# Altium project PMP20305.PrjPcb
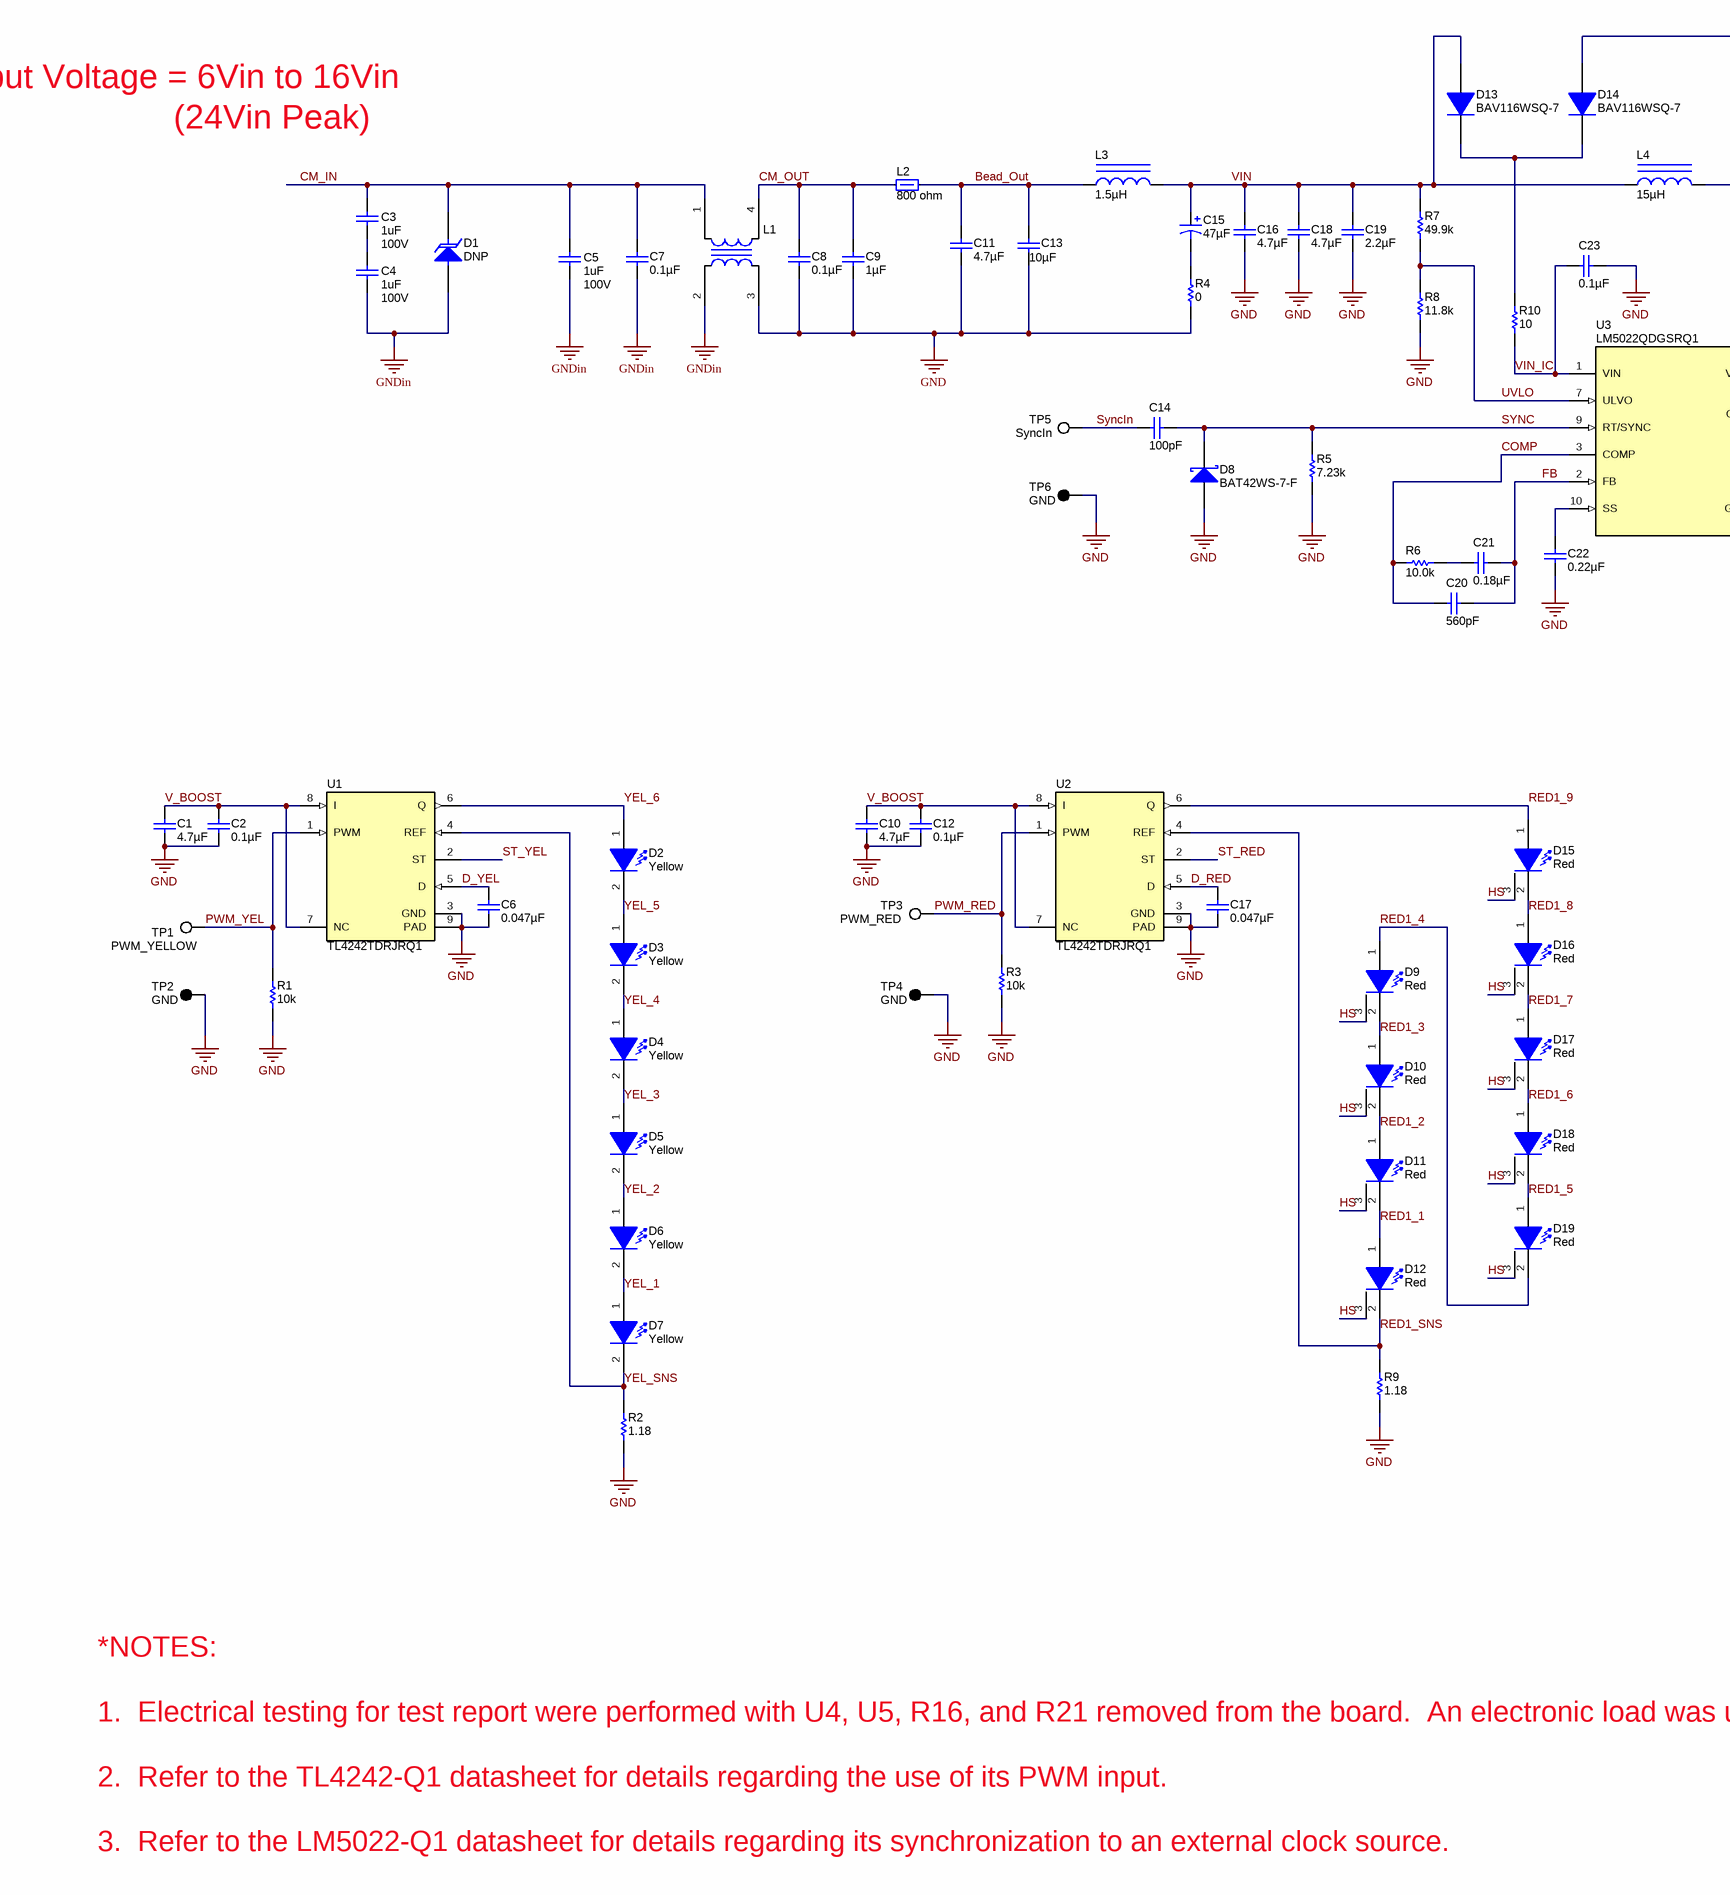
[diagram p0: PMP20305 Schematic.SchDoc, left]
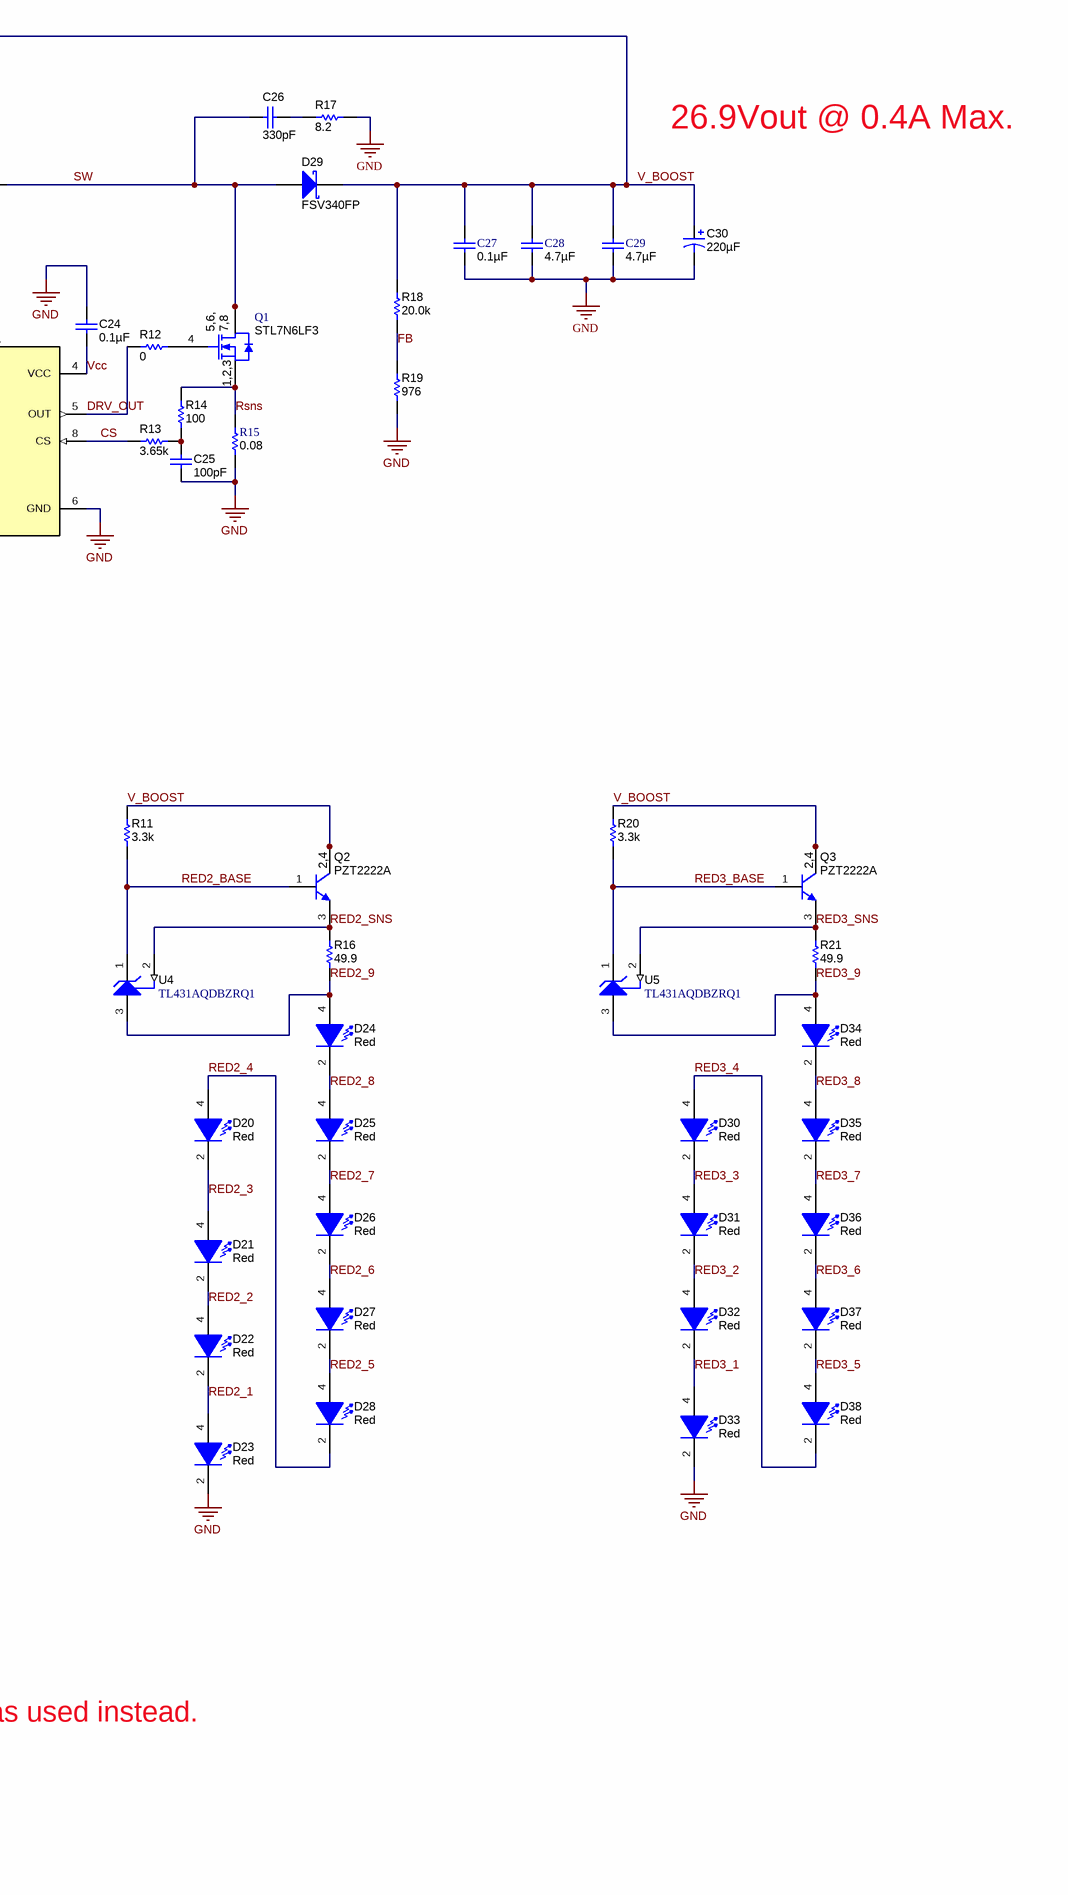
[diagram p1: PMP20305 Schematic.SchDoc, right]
CopyrightYear: 2016; PCB_Rev: A; PRJ_Number: PMP20305; PRJ_Title: LM5022 Non-Sync Boost with LED Drivers; SCH_Rev: A; TechSupport: http://www.ti.com/support; TID: PMP20305
2 sheets, 122 parts. Net scope: global (net labels, ports and power ports of the same name join across sheets).
Board file: PMP20305 PCB.PcbDoc
Sheets:
  PMP20305 Schematic.SchDoc
  PMP20305_EVM_Hardware.SchDoc

## Sheet PMP20305 Schematic.SchDoc
size 558 x 431 mm; Date: Not shown in title block; ApprovedBy: Not shown in title block; CheckedBy: Not shown in title block; Author: Not shown in title block; CompanyName: Not shown in title block; Engineer: Not shown in title block; Organization: Not shown in title block; Address1: Not shown in title block; Address2: Not shown in title block; Address3: Not shown in title block; Address4: Not shown in title block; DocumentNumber: 1; Revision: Use project parameter SCH_Rev; SheetNumber: 1; SheetTotal: 2; PageSetup: Record=PageOptions¦CenterHorizontal=True¦CenterVertical=True¦PrintScale=1.00¦XCorrection=1.00¦YCorrection=1.00¦PrintKind=0¦BorderSize=5000000¦LeftOffset=0¦BottomOffset=0¦Orientation=2¦PaperLength=1000¦PaperWidth=1000¦Scale=100¦PaperSource=15¦PrintQuality=600¦MediaType=1¦DitherType=10¦PaperKind=Letter¦PrintScaleMode=1

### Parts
C1  ValueDisplayed: 4.7µF  [1206_180]  (hidden comment: GRM31CR71H475KA12L)
C2  ValueDisplayed: 0.1µF  [0805_HV]  (hidden comment: 08055C104JAT2A)
C3  value 1uF  Value1: 100V  [0805]  (hidden comment: CGA4J3X7S2A105K125AB)
C4  value 1uF  Value1: 100V  [0805]  (hidden comment: CGA4J3X7S2A105K125AB)
C5  value 1uF  Value1: 100V  [0805]  (hidden comment: CGA4J3X7S2A105K125AB)
C6  ValueDisplayed: 0.047µF  [0603]  (hidden comment: GRM188R71C473KA01D)
C7  ValueDisplayed: 0.1µF  [0805_HV]  (hidden comment: CGA4J2X7R2A104K125AA)
C8  ValueDisplayed: 0.1µF  [0603]  (hidden comment: GRM188R71H104KA93D)
C9  ValueDisplayed: 1µF  [0603]  (hidden comment: UMK107AB7105KA-T)
C10  ValueDisplayed: 4.7µF  [1206_180]  (hidden comment: GRM31CR71H475KA12L)
C11  ValueDisplayed: 4.7µF  [1206_180]  (hidden comment: GRM31CR71H475KA12L)
C12  ValueDisplayed: 0.1µF  [0805_HV]  (hidden comment: 08055C104JAT2A)
C13  ValueDisplayed: 10µF  [1210_280]  (hidden comment: C3225X7R1H106M250AC)
C14  ValueDisplayed: 100pF  [0603]  (hidden comment: 06035A101JAT2A)
C15  ValueDisplayed: 47µF  [SM_RADIAL_G]  (hidden comment: EEE-FC1H470P)
C16  ValueDisplayed: 4.7µF  [1206_180]  (hidden comment: GRM31CR71H475KA12L)
C17  ValueDisplayed: 0.047µF  [0603]  (hidden comment: GRM188R71C473KA01D)
C18  ValueDisplayed: 4.7µF  [1206_180]  (hidden comment: GRM31CR71H475KA12L)
C19  ValueDisplayed: 2.2µF  [0805_HV]  (hidden comment: C2012X7R1H225K125AC)
C20  ValueDisplayed: 560pF  [0603]  (hidden comment: GRM1885C1E561JA01D)
C21  ValueDisplayed: 0.18µF  [0603]  (hidden comment: GRM188R71C184KA01D)
C22  ValueDisplayed: 0.22µF  [0603]  (hidden comment: GCM155R71C224KE02)
C23  ValueDisplayed: 0.1µF  [0805_HV]  (hidden comment: 08055C104JAT2A)
C24  ValueDisplayed: 0.1µF  [0603]  (hidden comment: 885012206071)
C25  ValueDisplayed: 100pF  [0603]  (hidden comment: 06035A101JAT2A)
C26  ValueDisplayed: 330pF  [0805_HV]  (hidden comment: C0805C331J1GACTU)
C27  ValueDisplayed: 0.1µF  [0603]  (hidden comment: CGA3E3X8R1H104K080AB)
C28  ValueDisplayed: 4.7µF  [1206_190]  (hidden comment: C3216X7R1H475M160AC)
C29  ValueDisplayed: 4.7µF  [1206_190]  (hidden comment: C3216X7R1H475M160AC)
C30  ValueDisplayed: 220µF  [SM_RADIAL_G]  (hidden comment: EEE-FC1V221P)
D1  DNP  [SMB]
D2  value Yellow  [LED_goldendragon]  (hidden comment: LY-W5SM)
D3  value Yellow  [LED_goldendragon]  (hidden comment: LY-W5SM)
D4  value Yellow  [LED_goldendragon]  (hidden comment: LY-W5SM)
D5  value Yellow  [LED_goldendragon]  (hidden comment: LY-W5SM)
D6  value Yellow  [LED_goldendragon]  (hidden comment: LY-W5SM)
D7  value Yellow  [LED_goldendragon]  (hidden comment: LY-W5SM)
D8  BAT42WS-7-F  [SOD-323]
D9  value Red  [LH CP7P_RED]  (hidden comment: LH CP7P-2T3T-1)
D10  value Red  [LH CP7P_RED]  (hidden comment: LH CP7P-2T3T-1)
D11  value Red  [LH CP7P_RED]  (hidden comment: LH CP7P-2T3T-1)
D12  value Red  [LH CP7P_RED]  (hidden comment: LH CP7P-2T3T-1)
D13  BAV116WSQ-7  [SOD-323]
D14  BAV116WSQ-7  [SOD-323]
D15  value Red  [LH CP7P_RED]  (hidden comment: LH CP7P-2T3T-1)
D16  value Red  [LH CP7P_RED]  (hidden comment: LH CP7P-2T3T-1)
D17  value Red  [LH CP7P_RED]  (hidden comment: LH CP7P-2T3T-1)
D18  value Red  [LH CP7P_RED]  (hidden comment: LH CP7P-2T3T-1)
D19  value Red  [LH CP7P_RED]  (hidden comment: LH CP7P-2T3T-1)
D20  value Red  [LED_PowerTOPLED_GF]  (hidden comment: LR-E6SF)
D21  value Red  [LED_PowerTOPLED_GF]  (hidden comment: LR-E6SF)
D22  value Red  [LED_PowerTOPLED_GF]  (hidden comment: LR-E6SF)
D23  value Red  [LED_PowerTOPLED_GF]  (hidden comment: LR-E6SF)
D24  value Red  [LED_PowerTOPLED_GF]  (hidden comment: LR-E6SF)
D25  value Red  [LED_PowerTOPLED_GF]  (hidden comment: LR-E6SF)
D26  value Red  [LED_PowerTOPLED_GF]  (hidden comment: LR-E6SF)
D27  value Red  [LED_PowerTOPLED_GF]  (hidden comment: LR-E6SF)
D28  value Red  [LED_PowerTOPLED_GF]  (hidden comment: LR-E6SF)
D29  FSV340FP  [SOD-123HE]
D30  value Red  [LED_PowerTOPLED_GF]  (hidden comment: LR-E6SF)
D31  value Red  [LED_PowerTOPLED_GF]  (hidden comment: LR-E6SF)
D32  value Red  [LED_PowerTOPLED_GF]  (hidden comment: LR-E6SF)
D33  value Red  [LED_PowerTOPLED_GF]  (hidden comment: LR-E6SF)
D34  value Red  [LED_PowerTOPLED_GF]  (hidden comment: LR-E6SF)
D35  value Red  [LED_PowerTOPLED_GF]  (hidden comment: LR-E6SF)
D36  value Red  [LED_PowerTOPLED_GF]  (hidden comment: LR-E6SF)
D37  value Red  [LED_PowerTOPLED_GF]  (hidden comment: LR-E6SF)
D38  value Red  [LED_PowerTOPLED_GF]  (hidden comment: LR-E6SF)
L1  ACM9070-701-2PL-TL01  [TDK_ACM9070]  (value not drawn)
L2  value 800 ohm  [1206]  (hidden comment: HR2220V801R-10)
L3  ValueDisplayed: 1.5µH  [WE-TPC_6823]  (hidden comment: 7440620015)
L4  ValueDisplayed: 15µH  [MSS1246T]  (hidden comment: MSS1246T-153MLB)
Q1  STL7N6LF3  [PowerFLAT5x6_R]
Q2  PZT2222A  [SOT-223]
Q3  PZT2222A  [SOT-223]
R1  ValueDisplayed: 10k  [0603]  (hidden comment: CRCW060310K0JNEA)
R2  ValueDisplayed: 1.18  [0805_HV]  (hidden comment: CRCW08051R18FKEA)
R3  ValueDisplayed: 10k  [0603]  (hidden comment: CRCW060310K0JNEA)
R4  ValueDisplayed: 0  [1206]  (hidden comment: CRCW12060000Z0EA)
R5  ValueDisplayed: 7.23k  [0603]  (hidden comment: RT0603DRE077K23L)
R6  ValueDisplayed: 10.0k  [0603]  (hidden comment: CRCW060310K0FKEA)
R7  ValueDisplayed: 49.9k  [0603]  (hidden comment: CRCW060349K9FKEA)
R8  ValueDisplayed: 11.8k  [0603]  (hidden comment: CRCW060311K8FKEA)
R9  ValueDisplayed: 1.18  [0805_HV]  (hidden comment: CRCW08051R18FKEA)
R10  ValueDisplayed: 10  [0603L]  (hidden comment: CRCW060310R0JNEA)
R11  ValueDisplayed: 3.3k  [0603]  (hidden comment: RC0603JR-073K3L)
R12  ValueDisplayed: 0  [0603]  (hidden comment: CRCW06030000Z0EA)
R13  ValueDisplayed: 3.65k  [0603]  (hidden comment: CRCW06033K65FKEA)
R14  ValueDisplayed: 100  [0603]  (hidden comment: CRCW0603100RJNEA)
R15  ValueDisplayed: 0.08  [2512]  (hidden comment: CRA2512-FZ-R080ELF)
R16  ValueDisplayed: 49.9  [2010]  (hidden comment: CRCW201049R9FKEF)
R17  ValueDisplayed: 8.2  [2512]  (hidden comment: CRCW25128R20JNEG)
R18  ValueDisplayed: 20.0k  [0603]  (hidden comment: RC0603FR-0720KL)
R19  ValueDisplayed: 976  [0603]  (hidden comment: RT0603DRE07976RL)
R20  ValueDisplayed: 3.3k  [0603]  (hidden comment: RC0603JR-073K3L)
R21  ValueDisplayed: 49.9  [2010]  (hidden comment: CRCW201049R9FKEF)
TP1  PWM_YELLOW  [Keystone5012]
TP2  GND  [Keystone5011]
TP3  PWM_RED  [Keystone5012]
TP4  GND  [Keystone5011]
TP5  SyncIn  [Keystone5012]
TP6  GND  [Keystone5011]
U1  TL4242TDRJRQ1  [DRJ0008A]
U2  TL4242TDRJRQ1  [DRJ0008A]
U3  LM5022QDGSRQ1  [DGS0010A_N]
U4  TL431AQDBZRQ1  [DBZ0003A_N]
U5  TL431AQDBZRQ1  [DBZ0003A_N]

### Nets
GND: C1.2 C2.2 C6.2 C8.1 C9.2 C10.2 C11.2 C12.2 C13.2 C16.2 C17.2 C18.2 C19.2 C22.2 C23.2 C24.1 C25.2 C27.2 C28.2 C29.2 C30.2(-) D8.2(A) D23.2(K) D33.2(K) L1.3 R1.1 R2.1 R3.1 R4.1 R5.1 R8.1 R9.1 R15.1 R17.2 R19.1 TP2.1 TP4.1 TP6.1 U1.3(GND) U1.9(PAD) U2.3(GND) U2.9(PAD) U3.6(GND)
GNDin: C4.2 C5.2 C7.2 D1.2(A) L1.2
Bead_Out: C11.1 C13.1 L2.2 L3.1
CM_IN: C3.1 C5.1 C7.1 D1.1(K) L1.1
CM_OUT: C8.2 C9.1 L1.4 L2.1
COMP: C20.2 R6.1 U3.3(COMP)
CS: R13.2 U3.8(CS)
D_RED: C17.1 U2.5(D)
D_YEL: C6.1 U1.5(D)
DRV_OUT: R12.1 U3.5(OUT)
FB: C20.1 C21.1 R18.1 R19.2 U3.2(FB)
HS: D9.3(HEATSINK) D10.3(HEATSINK) D11.3(HEATSINK) D12.3(HEATSINK) D15.3(HEATSINK) D16.3(HEATSINK) D17.3(HEATSINK) D18.3(HEATSINK) D19.3(HEATSINK)
PWM_RED: R3.2 TP3.1 U2.1(PWM)
PWM_YEL: R1.2 TP1.1 U1.1(PWM)
RED1_1: D11.2(K) D12.1(A)
RED1_2: D10.2(K) D11.1(A)
RED1_3: D9.2(K) D10.1(A)
RED1_4: D9.1(A) D19.2(K)
RED1_5: D18.2(K) D19.1(A)
RED1_6: D17.2(K) D18.1(A)
RED1_7: D16.2(K) D17.1(A)
RED1_8: D15.2(K) D16.1(A)
RED1_9: D15.1(A) U2.6(Q)
RED1_SNS: D12.2(K) R9.2 U2.4(REF)
RED2_1: D22.2(K) D23.4(A)
RED2_2: D21.2(K) D22.4(A)
RED2_3: D20.2(K) D21.4(A)
RED2_4: D20.4(A) D28.2(K)
RED2_5: D27.2(K) D28.4(A)
RED2_6: D26.2(K) D27.4(A)
RED2_7: D25.2(K) D26.4(A)
RED2_8: D24.2(K) D25.4(A)
RED2_9: D24.4(A) R16.1 U4.3(ANODE)
RED2_BASE: Q2.1(B) R11.1 U4.1(CATHODE)
RED2_SNS: Q2.3(E) R16.2 U4.2(REF)
RED3_1: D32.2(K) D33.4(A)
RED3_2: D31.2(K) D32.4(A)
RED3_3: D30.2(K) D31.4(A)
RED3_4: D30.4(A) D38.2(K)
RED3_5: D37.2(K) D38.4(A)
RED3_6: D36.2(K) D37.4(A)
RED3_7: D35.2(K) D36.4(A)
RED3_8: D34.2(K) D35.4(A)
RED3_9: D34.4(A) R21.1 U5.3(ANODE)
RED3_BASE: Q3.1(B) R20.1 U5.1(CATHODE)
RED3_SNS: Q3.3(E) R21.2 U5.2(REF)
Rsns: Q1.1(S) Q1.2(S) Q1.3(S) R14.2 R15.2
ST_RED: U2.2(ST)
ST_YEL: U1.2(ST)
SW: C26.2 D29.2(A) L4.2 Q1.5(D) Q1.6(D) Q1.7(D) Q1.8(D) Q1.9(D)
SYNC: C14.2 D8.1(K) R5.2 U3.9(RT/SYNC)
SyncIn: C14.1 TP5.1
UVLO: R7.1 R8.2 U3.7(ULVO)
V_BOOST: C1.1 C2.1 C10.1 C12.1 C27.1 C28.1 C29.1 C30.1(+) D14.2(A) D29.1(K) Q2.2(C) Q2.4(C) Q3.2(C) Q3.4(C) R11.2 R18.2 R20.2 U1.7(NC) U1.8(I) U2.7(NC) U2.8(I)
Vcc: C24.2 U3.4(VCC)
VIN: C15.1(+) C16.1 C18.1 C19.1 D13.2(A) L3.2 L4.1 R7.2
VIN_IC: C23.1 R10.1 U3.1(VIN)
YEL_1: D6.2(K) D7.1(A)
YEL_2: D5.2(K) D6.1(A)
YEL_3: D4.2(K) D5.1(A)
YEL_4: D3.2(K) D4.1(A)
YEL_5: D2.2(K) D3.1(A)
YEL_6: D2.1(A) U1.6(Q)
YEL_SNS: D7.2(K) R2.2 U1.4(REF)
NetC3_2: C3.2 C4.1
NetC15_2: C15.2(-) R4.2
NetC21_2: C21.2 R6.2
NetC22_1: C22.1 U3.10(SS)
NetC25_1: C25.1 R13.1 R14.1
NetC26_1: C26.1 R17.1
NetD13_1: D13.1(K) D14.1(K) R10.2
NetQ1_4: Q1.4(G) R12.2

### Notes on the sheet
- Input Voltage = 6Vin to 16Vin
- (24Vin Peak)
- 26.9Vout @ 0.4A Max.
- *NOTES:
  1.  Electrical testing for test report were performed with U4, U5, R16, and R21 removed from the board.  An electronic load was used instead.
  2.  Refer to the TL4242-Q1 datasheet for details regarding the use of its PWM input.
  3.  Refer to the LM5022-Q1 datasheet for details regarding its synchronization to an external clock source.

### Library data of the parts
C1 C10 C16 C18 = GRM31CR71H475KA12L: CAP, CERM, 4.7 µF, 50 V, +/- 10%, X7R, 1206; Manufacturer: MuRata; Polarized: N; CompType: Capacitor; Value: 4.7uF; U/M: EA; Cap_F: 0.0000047; Tolerance_%: 10; Value1: Unknown; VDC_V: 50; Value2: 50V; TaMin_C: -55; TaMax_C: 125; Cap_Case: 2220; AEC Category: Q200; SizeArea_mm2: 5.12; SizeAreaWB_mm2: 10.92; SizeX_mm: 3.2; SizeY_mm: 1.6; SizeZ_mm: 1.8
C2 C12 C23 = 08055C104JAT2A: CAP, CERM, 0.1 µF, 50 V, +/- 5%, X7R, 0805; Manufacturer: AVX; Polarized: N; CompType: Capacitor; Value: 0.1uF; U/M: EA; Cap_F: 0.0000001; Tolerance_%: 5; ESR_ohm: 0.024; Value1: 0.024 ohm; VDC_V: 50; Value2: 50V; TaMin_C: -55; TaMax_C: 125; Cap_Case: 0805; AEC Category: Q200
C3-C5 = Capacitor: CAP, CERM, 1uF, 100V, X7S, 10%, 0805; Manufacturer: TDK; Polarized: N; U/M: EA
C6 C17 = GRM188R71C473KA01D: CAP, CERM, 0.047 µF, 16 V, +/- 10%, X7R, 0603; Manufacturer: MuRata; Polarized: N; CompType: Capacitor; Value: 0.047uF; U/M: EA; Cap_F: 0.000000047; Tolerance_%: 10; Value1: Unknown; VDC_V: 16; Value2: 16V; TaMin_C: -55; TaMax_C: 125; AEC Category: Q200; SizeArea_mm2: 1.28; SizeAreaWB_mm2: 4.68; SizeX_mm: 1.6; SizeY_mm: 0.8; SizeZ_mm: 1
C7 = CGA4J2X7R2A104K125AA: CAP, CERM, 0.1 µF, 100 V, +/- 10%, X7R, AEC-Q200 Grade 1, 0805; Manufacturer: TDK; Polarized: N; CompType: Capacitor; Value: 0.1uF; U/M: EA; Cap_F: 0.0000001; Tolerance_%: 10; ESR_ohm: 0.020726; Value1: 0.020726 ohm; VDC_V: 100; Value2: 100V; IRMS_A: 1.456; TaMin_C: -55; TaMax_C: 125; Cap_Case: 0805; SizeArea_mm2: 2.5; SizeAreaWB_mm2: 6.75; SizeX_mm: 2; SizeY_mm: 1.25; SizeZ_mm: 1.45; AEC Category: Q200; AEC Qualified: Y; AEC Grade: 1
C8 = GRM188R71H104KA93D: CAP, CERM, 0.1 µF, 50 V, +/- 10%, X7R, 0603; Manufacturer: MuRata; Polarized: N; CompType: Capacitor; Value: 0.1uF; U/M: EA; Cap_F: 0.0000001; Tolerance_%: 10; Value1: Unknown; VDC_V: 50; Value2: 50V; TaMin_C: -55; TaMax_C: 125; AEC Category: Q200
C9 = UMK107AB7105KA-T: CAP, CERM, 1 µF, 50 V, +/- 10%, X7R, 0603; Manufacturer: Taiyo Yuden; Polarized: N; CompType: Capacitor; Value: 1uF; U/M: EA; Value1: Unknown; Cap_F: 0.000001; Tolerance_%: 10; VDC_V: 50; Value2: 50V; TaMin_C: -55; TaMax_C: 125; AEC Category: Q200
C11 = GRM31CR71H475KA12L: CAP, CERM, 4.7 µF, 50 V, +/- 10%, X7R, 1206; Manufacturer: MuRata; CompType: Capacitor; U/M: EA; Tolerance_%: 10; Value: 4.7uF; VDC_V: 50; Polarized: N; Cap_F: 0.0000047; Value1: Unknown; Value2: 50V; TaMin_C: -55; TaMax_C: 125; Cap_Case: 2220; SizeArea_mm2: 5.12; SizeAreaWB_mm2: 10.92; SizeX_mm: 3.2; SizeY_mm: 1.6; SizeZ_mm: 1.8; AEC Category: Q200
C13 = C3225X7R1H106M250AC: CAP, CERM, 10 µF, 50 V, +/- 20%, X7R, 1210; Manufacturer: TDK; Polarized: N; CompType: Capacitor; Value: 10uF; U/M: EA; Cap_F: 0.00001; Tolerance_%: 20; Value1: Unknown; VDC_V: 50; Value2: 50V; TaMin_C: -55; TaMax_C: 125; Cap_Case: 1210
C14 C25 = 06035A101JAT2A: CAP, CERM, 100 pF, 50 V, +/- 5%, C0G/NP0, 0603; Manufacturer: AVX; Polarized: N; CompType: Capacitor; Value: 100pF; U/M: EA; Cap_F: 0.0000000001; Tolerance_%: 5; ESR_ohm: 0.119; Value1: 0.119 ohm; VDC_V: 50; Value2: 50V; TaMin_C: -55; TaMax_C: 125; AEC Category: Q200
C15 = EEE-FC1H470P: CAP, AL, 47 µF, 50 V, +/- 20%, 0.3 ohm, SMD; Manufacturer: Panasonic; Polarized: Y; CompType: Capacitor; Value: 47uF; U/M: EA; Cap_F: 0.000047; Tolerance_%: 20; Value1: 0.3 ohm; VDC_V: 50; Value2: 50V; ESR_ohm: 0.3; IRMS_A: 0.5; TaMin_C: -40; TaMax_C: 105; Cap_Case: G
C19 = C2012X7R1H225K125AC: CAP, CERM, 2.2 µF, 50 V, +/- 10%, X7R, 0805; Manufacturer: TDK; Polarized: N; CompType: Capacitor; Value: 2.2uF; U/M: EA; Cap_F: 0.0000022; Tolerance_%: 10; Value1: Unknown; VDC_V: 50; Value2: 50V; TaMin_C: -55; TaMax_C: 125; Cap_Case: 0805; AEC Category: Q200
C20 = GRM1885C1E561JA01D: CAP, CERM, 560 pF, 25 V, +/- 5%, C0G/NP0, 0603; Manufacturer: MuRata; Polarized: N; CompType: Capacitor; Value: 560pF; U/M: EA; Cap_F: 0.00000000056; Tolerance_%: 5; Value1: Unknown; VDC_V: 25; Value2: 25V; TaMin_C: -55; TaMax_C: 125; AEC Category: Q200; SizeArea_mm2: 1.28; SizeAreaWB_mm2: 4.68; SizeX_mm: 1.6; SizeY_mm: 0.8; SizeZ_mm: 1
C21 = GRM188R71C184KA01D: CAP, CERM, 0.18 µF, 16 V, +/- 10%, X7R, 0603; Manufacturer: MuRata; Polarized: N; CompType: Capacitor; Value: 0.18uF; U/M: EA; Cap_F: 0.00000018; Tolerance_%: 10; Value1: Unknown; VDC_V: 16; Value2: 16V; TaMin_C: -55; TaMax_C: 125; AEC Category: Q200; SizeArea_mm2: 1.28; SizeAreaWB_mm2: 4.68; SizeX_mm: 1.6; SizeY_mm: 0.8; SizeZ_mm: 1
C22 = GCM155R71C224KE02: CAP, CERM, 0.22 µF, 16 V, +/- 10%, X7R, AEC-Q200 Grade 1, 0603; Manufacturer: MuRata; Polarized: N; CompType: Capacitor; Value: 0.22uF; U/M: EA; Cap_F: 0.00000022; Tolerance_%: 10; Value1: Unknown; VDC_V: 16; Value2: 16V; TaMin_C: -55; TaMax_C: 125; AEC Category: Q200; AEC Qualified: Y; AEC Grade: 1; SizeArea_mm2: 1.28; SizeAreaWB_mm2: 4.68; SizeX_mm: 1.6; SizeY_mm: 0.8
C24 = 885012206071: CAP, CERM, 0.1 µF, 25 V, +/- 10%, X7R, 0603; Manufacturer: Wurth Elektronik; Polarized: N; CompType: Capacitor; Value: 0.1uF; U/M: EA; Cap_F: 0.0000001; Tolerance_%: 10; Value1: Unknown; VDC_V: 25; Value2: 25V; TaMin_C: -55; TaMax_C: 125; AEC Category: Q200
C26 = C0805C331J1GACTU: CAP, CERM, 330 pF, 100 V, +/- 5%, C0G/NP0, 0805; Manufacturer: Kemet; Polarized: N; CompType: Capacitor; Value: 330pF; U/M: EA; Cap_F: 0.00000000033; Tolerance_%: 5; ESR_ohm: 0.038; Value1: 0.038 ohm; VDC_V: 100; Value2: 100V; IRMS_A: 1.04; TaMin_C: -55; TaMax_C: 125; Cap_Case: 0805; AEC Category: Q200
C27 = CGA3E3X8R1H104K080AB: CAP, CERM, 0.1 µF, 50 V, +/- 10%, X8R, AEC-Q200 Grade 0, 0603; Manufacturer: TDK; Polarized: N; CompType: Capacitor; Value: 0.1uF; U/M: EA; Cap_F: 0.0000001; Tolerance_%: 10; Value1: Unknown; VDC_V: 50; Value2: 50V; TaMin_C: -55; TaMax_C: 150; AEC Category: Q200; AEC Qualified: Y; AEC Grade: 0
C28 C29 = C3216X7R1H475M160AC: CAP, CERM, 4.7 µF, 50 V, +/- 20%, X7R, 1206_190; Manufacturer: TDK; Polarized: N; CompType: Capacitor; Value: 4.7uF; U/M: EA; Cap_F: 0.0000047; Tolerance_%: 20; Value1: Unknown; VDC_V: 50; Value2: 50V; TaMin_C: -55; TaMax_C: 125; Cap_Case: 1206; AEC Category: Q200
C30 = EEE-FC1V221P: CAP, AL, 220 µF, 35 V, +/- 20%, 0.15 ohm, SMD; Manufacturer: Panasonic; Polarized: Y; CompType: Capacitor; Value: 220uF; U/M: EA; Cap_F: 0.00022; Tolerance_%: 20; VDC_V: 35; Value2: 35V; ESR_ohm: 0.15; IRMS_A: 0.67; TaMin_C: -40; TaMax_C: 105; Cap_Case: G; AEC Category: Q200
D1 = SMBJ22A-13-F: Diode, TVS, Uni, 22 V, 600 W, SMB; Manufacturer: Diodes Inc.; Value: 22V; U/M: EA; Power_W: 5; Vr_V: 22; Value1: 5W; SizeAreaWB_mm2: 44.156; SizeArea_mm2: 21.336; SizeX_mm: 5.6; SizeY_mm: 3.81; SizeZ_mm: 2.6; AEC Category: Q101
D2-D7 = LY-W5SM: LED, Yellow, SMD; Manufacturer: OSRAM; Type: AlInGaP; Vf_V: 2.2; Value2: 2.2V; Io_A: 0.4; RJC_CperW: 15; Tjmax_C: 125; Power_TotalModule: 0.88; Value1: 0.88W; LambdaP: 595; LambdaD: 590; NumParallelLEDs: 1; LuminousIntensity_IV: 12.6; LuminousFlux_PhiV: 38; Angle: 120; FamilyName: Golden DRAGON&#174;; U/M: EA
D8 = BAT42WS-7-F: Diode, Schottky, 30 V, 0.2 A, SOD-323; Manufacturer: Diodes Inc.; U/M: EA; Vf_V: 1; Value: 30V; Value1: 0.2A; Value2: 1V; Io_A: 0.2; Vr_V: 30; SizeAreaWB_mm2: 8.695; SizeArea_mm2: 3.645; SizeX_mm: 2.7; SizeY_mm: 1.35; AEC Category: Q101
D9-D12 D15-D19 = LH CP7P-2T3T-1: LED, Red, SMD; Manufacturer: OSRAM; Vf_V: 2.1; Value2: 2.1V; Io_A: 0.35; Tjmax_C: 135; Value1: W; Angle: 80; U/M: EA; SymbolCreator: a0412235
D13 D14 = Diode: Diode, Standard, 85V, 215mA, SOD-323, AEC-Q101; Manufacturer: Diodes Inc.; U/M: EA
D20-D28 D30-D38 = LR-E6SF: LED, Red, SMD; Manufacturer: OSRAM; Vf_V: 2.15; Value2: 2.15V; Io_A: 0.05; Vr_V: 12; RJC_CperW: 130; Tjmax_C: 125; Power_TotalModule: 0.1075; Value1: 0.1075W; LambdaP: 634; LambdaD: 625; NumParallelLEDs: 1; LuminousFlux_PhiV: 5.8; Angle: 120; FamilyName: Power TOPLED&#174;; U/M: EA
D29 = FSV340FP: Diode, Schottky, 40 V, 3 A, AEC-Q101, SOD-123HE; Manufacturer: Fairchild Semiconductor; U/M: EA; Vf_V: 0.52; Value: 40V; Value1: 3A; Value2: 0.52V; Io_A: 3; Vr_V: 40; TJmax_C: 150; AEC Category: Q101; AEC Qualified: Y
L1 = ACM9070-701-2PL-TL01: Coupled inductor, 5 A, 0.01 ohm, SMD; Manufacturer: TDK; SymbolCreator: a0799628; DCR_ohm: 0.01
L2 = HR2220V801R-10: Ferrite Bead, 800 ohm @ 100 MHz, 8 A, 1206; Manufacturer: Laird-Signal Integrity Products; Imax_A: 8; DCR_ohm: 0.01; Value1: 0.01 ohm; Value2: 8A; ZTyp@100MHz_Ohm: 800; Ztyp@1GHz_Ohm: 75
L3 = 7440620015: Inductor, Shielded Drum Core, Metal Composite, 1.5 µH, 4 A, 0.01 ohm, SMD; Manufacturer: Wurth Elektronik; Value: 1.5uH; Ind_H: 1.5E-6; Imax_A: 4; Irms: 4.3A @ 30C rise; Isat: 4A @ 35% inductance drop; DCR_ohm: 0.01; Value2: 4A; AEC Category: Q200
L4 = MSS1246T-153MLB: Inductor, Shielded Drum Core, Ferrite, 15 µH, 3.4 A, 0.05 ohm, SMD; Manufacturer: Coilcraft; Value: 15uH; Ind_H: 15.0E-6; Imax_A: 3.4; Irms: 3.4A @ 40C rise; Isat: 5.78A @ 30% inductance drop; DCR_ohm: 0.05; Value2: 3.4A; AEC Category: Q200
Q1 = STL7N6LF3: MOSFET, N-CH, 60 V, 20 A, AEC-Q101, 8-PowerVDFN; Manufacturer: STMicroelectronics; Alternate Manufacturer: None; U/M: EA; ChType: N; Value: 60V; VdsMax_V: 60; Value1: ? ohm; Value2: 8.7 nC; QgTyp_nC: 8.7; Vgs_V: 20; AEC Category: Q101; AEC Qualified: Y
Q2 Q3 = PZT2222A, Fairchild Semiconductor: Transistor, NPN, 40 V, 1 A, SOT-223; SymbolCreator: a0412235; PNP: 0; NPN: 1; Vceo_V: 40; Value: 40 V; Value1: 1 A; HfeMax: 300; TaMin_C: -55; TaMax_C: 150; CompType: BJT; U/M: EA; AEC Category: Q101
R1 R3 = CRCW060310K0JNEA: RES, 10 k, 5%, 0.1 W, 0603; Manufacturer: Vishay-Dale; CompType: Resistor; Value: 10k; Res_ohm: 10000; Value_Code: 10k0; Tolerance_%: 5; Power_W: 0.1; Value2: 0.1W; VDC_V: 75; TempCo: 200 ppm/C; EIA_Code: E24; U/M: EA; AEC Category: Q200; SizeArea_mm2: 1.28; SizeX_mm: 1.6; SizeY_mm: 0.8; SizeZ_mm: 1
R2 R9 = CRCW08051R18FKEA: RES, 1.18, 1%, 0.125 W, 0805; Manufacturer: Vishay-Dale; CompType: Resistor; Value: 1.18; Value_Code: 1R18; Tolerance_%: 1; Power_W: 0.125; Value2: 0.125W; VDC_V: 150; TempCo: 100 ppm/C; EIA_Code: E96; U/M: EA; AEC Category: Q200
R4 = CRCW12060000Z0EA: RES, 0, 5%, 0.25 W, 1206; Manufacturer: Vishay-Dale; CompType: Resistor; Value: 0; Value_Code: 0000; Tolerance_%: 5; Power_W: 0.25; Value2: 0.25W; VDC_V: 200; TempCo: 200 ppm/C; EIA_Code: E24; U/M: EA; SizeArea_mm2: 5.12; SizeX_mm: 3.2; SizeY_mm: 1.6; SizeZ_mm: 1.35; AEC Category: Q200
R5 = RT0603DRE077K23L: RES, 7.23 k, 0.5%, 0.1 W, 0603; Manufacturer: Yageo America; CompType: Resistor; Value: 7.23k; Res_ohm: 7230; Value_Code: 7k23; Tolerance_%: 0.5; Power_W: 0.1; Value2: 0.1W; VDC_V: 75; TempCo: 50 ppm/C; EIA_Code: E192; U/M: EA; AEC Category: Q200
R6 = CRCW060310K0FKEA: RES, 10.0 k, 1%, 0.1 W, 0603; Manufacturer: Vishay-Dale; CompType: Resistor; Value: 10.0k; Res_ohm: 10000; Value_Code: 10k0; Tolerance_%: 1; Power_W: 0.1; Value2: 0.1W; VDC_V: 75; TempCo: 100 ppm/C; EIA_Code: E96; U/M: EA; AEC Category: Q200; SizeArea_mm2: 1.28; SizeX_mm: 1.6; SizeY_mm: 0.8
R7 = CRCW060349K9FKEA: RES, 49.9 k, 1%, 0.1 W, 0603; Manufacturer: Vishay-Dale; CompType: Resistor; Value: 49.9k; Res_ohm: 49900; Value_Code: 49k9; Tolerance_%: 1; Power_W: 0.1; Value2: 0.1W; VDC_V: 75; TempCo: 100 ppm/C; EIA_Code: E96; U/M: EA; AEC Category: Q200; SizeArea_mm2: 1.28; SizeX_mm: 1.6; SizeY_mm: 0.8
R8 = CRCW060311K8FKEA: RES, 11.8 k, 1%, 0.1 W, 0603; Manufacturer: Vishay-Dale; CompType: Resistor; Value: 11.8k; Res_ohm: 11800; Value_Code: 11k8; Tolerance_%: 1; Power_W: 0.1; Value2: 0.1W; VDC_V: 75; TempCo: 100 ppm/C; EIA_Code: E96; U/M: EA; AEC Category: Q200; SizeArea_mm2: 1.28; SizeX_mm: 1.6; SizeY_mm: 0.8
R10 = CRCW060310R0JNEA: RES, 10, 5%, 0.1 W, 0603; Manufacturer: Vishay-Dale; CompType: Resistor; Value: 10; U/M: EA; Value_Code: 10R0; Tolerance_%: 5; Power_W: 0.1; Value2: 0.1W; VDC_V: 75; TempCo: 200 ppm/C; EIA_Code: E24; AEC Category: Q200
R11 R20 = RC0603JR-073K3L: RES, 3.3 k, 5%, 0.1 W, 0603; Manufacturer: Yageo America; CompType: Resistor; Value: 3.3k; Res_ohm: 3300; Value_Code: 3k30; Tolerance_%: 5; Power_W: 0.1; Value2: 0.1W; VDC_V: 50; TempCo: 100 ppm/C; EIA_Code: E24; U/M: EA; AEC Category: Q200
R12 = CRCW06030000Z0EA: RES, 0, 5%, 0.1 W, 0603; Manufacturer: Vishay-Dale; CompType: Resistor; Value: 0; Value_Code: 0000; Tolerance_%: 5; Power_W: 0.1; Value2: 0.1W; VDC_V: 75; TempCo: 200 ppm/C; EIA_Code: E24; U/M: EA; AEC Category: Q200; SizeArea_mm2: 1.28; SizeX_mm: 1.6; SizeY_mm: 0.8; SizeZ_mm: 1
R13 = CRCW06033K65FKEA: RES, 3.65 k, 1%, 0.1 W, 0603; Manufacturer: Vishay-Dale; CompType: Resistor; Value: 3.65k; Res_ohm: 3650; Value_Code: 3k65; Tolerance_%: 1; Power_W: 0.1; Value2: 0.1W; VDC_V: 75; TempCo: 100 ppm/C; EIA_Code: E96; U/M: EA; AEC Category: Q200; SizeArea_mm2: 1.28; SizeX_mm: 1.6; SizeY_mm: 0.8
R14 = CRCW0603100RJNEA: RES, 100, 5%, 0.1 W, 0603; Manufacturer: Vishay-Dale; CompType: Resistor; Value: 100; Value_Code: 100R; Tolerance_%: 5; Power_W: 0.1; Value2: 0.1W; VDC_V: 75; TempCo: 200 ppm/C; EIA_Code: E24; U/M: EA; AEC Category: Q200
R15 = CRA2512-FZ-R080ELF: RES, 0.08, 1%, 3 W, 2512; Manufacturer: Bourns; CompType: Resistor; Value: 0.08; Value_Code: R080; Tolerance_%: 1; Power_W: 3; Value2: 3W; VDC_V: 0; TempCo: 75 ppm/C; U/M: EA; AEC Category: Q200; SizeArea_mm2: 20.16; SizeX_mm: 6.3; SizeY_mm: 3.2; SizeZ_mm: 0.71
R16 R21 = CRCW201049R9FKEF: RES, 49.9, 1%, 0.75 W, AEC-Q200 Grade 0, 2010; Manufacturer: Vishay-Dale; CompType: Resistor; Value: 49.9; Value_Code: 49R9; Tolerance_%: 1; Power_W: 0.75; Value2: 0.75W; VDC_V: 400; TempCo: 100 ppm/C; EIA_Code: E96; U/M: EA; AEC Category: Q200; AEC Qualified: Y; AEC Grade: 0
R17 = CRCW25128R20JNEG: RES, 8.2, 5%, 1 W, AEC-Q200 Grade 0, 2512; Manufacturer: Vishay-Dale; CompType: Resistor; Value: 8.2; Value_Code: 8R20; Tolerance_%: 5; Power_W: 1; Value2: 1W; VDC_V: 500; TempCo: 200 ppm/C; EIA_Code: E24; U/M: EA; AEC Category: Q200; AEC Qualified: Y; AEC Grade: 0
R18 = RC0603FR-0720KL: RES, 20.0 k, 1%, 0.1 W, 0603; Manufacturer: Yageo America; CompType: Resistor; Value: 20.0k; Res_ohm: 20000; Value_Code: 20k0; Tolerance_%: 1; Power_W: 0.1; Value2: 0.1W; VDC_V: 150; TempCo: 200 ppm/C; EIA_Code: E96; U/M: EA; AEC Category: Q200
R19 = RT0603DRE07976RL: RES, 976, 0.5%, 0.1 W, 0603; Manufacturer: Yageo America; CompType: Resistor; Value: 976; Value_Code: 976R; Tolerance_%: 0.5; Power_W: 0.1; Value2: 0.1W; VDC_V: 75; TempCo: 50 ppm/C; EIA_Code: E192; U/M: EA; AEC Category: Q200
TP1 TP3 TP5 = 5012: Test Point, Multipurpose, White, TH; Manufacturer: Keystone; CompType: Test Point Loop; ContactFinish: Silver
TP2 TP4 TP6 = 5011: Test Point, Multipurpose, Black, TH; Manufacturer: Keystone; CompType: Test Point Loop; U/M: EA
U1 U2 = TL4242TDRJRQ1: ADJUSTABLE LED DRIVER, DRJ0008A; Manufacturer: Texas Instruments; SymbolCreator: a0411947; CompType: IC; U/M: EA
U3 = LM5022QDGSRQ1: 60V Low Side Controller for Boost and SEPIC, DGS0010A; Alternate PartNumber: LM5022QDGSTQ1; Manufacturer: Texas Instruments; SymbolCreator: a0411947; CompType: IC; U/M: EA
U4 U5 = TL431AQDBZRQ1: Automotive Catalog Adjustable Precision Shunt Regulator, 34 ppm / degC, 100 mA, -40 to 125 degC, 3-pin SOT-23 (DBZ), Green (RoHS & no Sb/Br); Manufacturer: Texas Instruments; Alternate PartNumber: Equivalent; Initial Accuracy @ 25/deg C(%): 1; Iout/Iz(Max)(mA): 100; Min Iz for Regulation(uA): 600; SubFamily: Shunt Voltage Reference; Temp Coeff(Typ)(ppm/ degree C): 34; VO Adj(Max)(V): 36; VO Adj(Min)(V): 2.495

## Sheet PMP20305_EVM_Hardware.SchDoc: Hardware
size 431 x 279 mm; Date: Not shown in title block; ApprovedBy: Not shown in title block; CheckedBy: Not shown in title block; Author: Not shown in title block; CompanyName: Not shown in title block; Engineer: Not shown in title block; Organization: Not shown in title block; Address1: Not shown in title block; Address2: Not shown in title block; Address3: Not shown in title block; Address4: Not shown in title block; DocumentNumber: 2; Revision: Use project parameter SCH_Rev; SheetNumber: 2; SheetTotal: 2; PageSetup: Record=PageOptions¦CenterHorizontal=True¦CenterVertical=True¦PrintScale=1.00¦XCorrection=1.00¦YCorrection=1.00¦PrintKind=0¦BorderSize=5000000¦LeftOffset=0¦BottomOffset=0¦Orientation=2¦PaperLength=1000¦PaperWidth=1000¦Scale=100¦PaperSource=15¦PrintQuality=600¦MediaType=1¦DitherType=10¦PaperKind=Letter¦PrintScaleMode=1
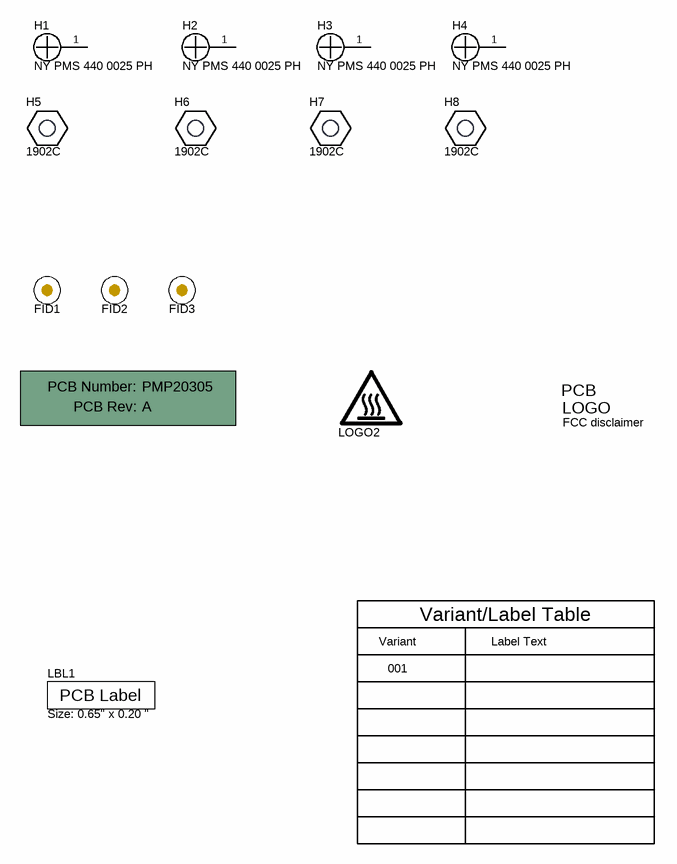
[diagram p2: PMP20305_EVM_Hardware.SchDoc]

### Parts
!PCB1  Printed Circuit Board  (value not drawn)  (mechanical)
FID1  Fiducial  [Fiducial10-20]  (value not drawn)
FID2  Fiducial  [Fiducial10-20]  (value not drawn)
FID3  Fiducial  [Fiducial10-20]  (value not drawn)
H1  NY PMS 440 0025 PH  [NY PMS 440 0025 PH]
H2  NY PMS 440 0025 PH  [NY PMS 440 0025 PH]
H3  NY PMS 440 0025 PH  [NY PMS 440 0025 PH]
H4  NY PMS 440 0025 PH  [NY PMS 440 0025 PH]
H5  1902C  [Keystone_1902C]
H6  1902C  [Keystone_1902C]
H7  1902C  [Keystone_1902C]
H8  1902C  [Keystone_1902C]
LBL1  Size: 0.65" x 0.20 "  [Label_650x200]
Logo1  FCC disclaimer  [FCC_disclaimer]  (no BOM)
LOGO2  CAUTION HOT SURFACE  [IEC_HotSurface_Medium]  (value not drawn)  (no BOM)

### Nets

Not connected (* = marked no-connect by the designer): H1 1; H2 1; H3 1; H4 1

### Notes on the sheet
- Variant
- Variant/Label Table
- Label Text
- 001

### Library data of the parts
!PCB1 = PCB: Manufacturer: Any; PartNumber: PMP20305; SymbolCreator: a0412235
FID1-FID3 = Fiducial: Fiducial mark.  There is nothing to buy or mount.; SymbolCreator: codlsc
H1-H4 = NY PMS 440 0025 PH: Machine Screw, Round, #4-40 x 1/4, Nylon, Philips panhead; Manufacturer: B&F Fastener Supply; CompType: Hardware; SymbolCreator: codlsc; U/M: EA
H5-H8 = 1902C: Standoff, Hex, 0.5"L #4-40 Nylon; Manufacturer: Keystone; CompType: Hardware
LBL1 = THT-14-423-10: Thermal Transfer Printable Labels, 0.650" W x 0.200" H - 10,000 per roll; Manufacturer: Brady; SymbolCreator: a0412235; CompType: Label
Logo1 = FCC_disclaimer: SymbolCreator: codlsc
LOGO2 = IEC_HotSurface: IEC 61010-1 Hot Surface Warning; SymbolCreator: a0412235

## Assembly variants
001: not fitted D1 FID1 FID2 FID3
